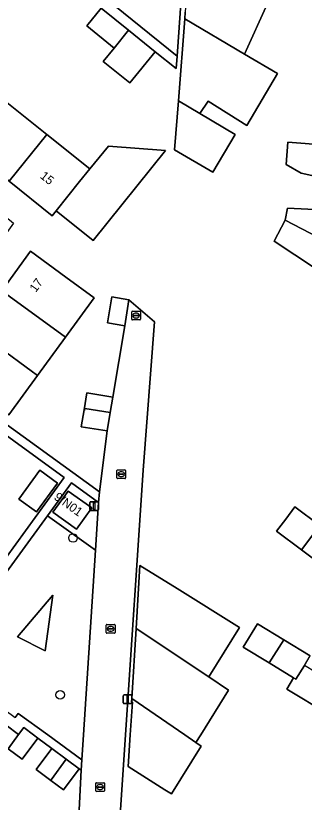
# Model space of a CAD drawing. Extents: x 160102 to 160934, y 382045 to 382923.
# Drawn here: x 160503.3 to 160536.3, y 382492.3 to 382582.2 of the extents above; entities that cross this region are included whole.
import ezdxf

# ---------------------------------------------------------------- set-up
doc = ezdxf.new("R2010")
doc.units = 0
for name, color, linetype in [('IMGEO_Boom', 7, 'Continuous'), ('IMGEO_Erf', 7, 'Continuous'), ('IMGEO_Groenvoorziening', 7, 'Continuous'), ('IMGEO_Kolk', 7, 'Continuous'), ('IMGEO_Lichtmast', 7, 'Continuous'), ('IMGEO_Pand', 7, 'Continuous'), ('IMGEO_Pand_nummerreeks', 7, 'Continuous'), ('IMGEO_Rijbaan_lokaal_open', 7, 'Continuous'), ('IMGEO_Voetpad_open', 7, 'Continuous')]:
    doc.layers.add(name, color=color, linetype=linetype)

msp = doc.modelspace()

# ---------------------------------------------------------------- linework, layer by layer
at = {"layer": 'IMGEO_Boom'}
for centre in [(160509.882, 382522.501), (160508.408, 382504.588)]:
    msp.add_circle(centre, 0.489, dxfattribs=at)
at = {"layer": 'IMGEO_Erf'}
for points in [[(160522.529, 382588.511), (160521.777, 382577.568), (160521.653, 382576.138), (160519.258, 382578.07), (160516.366, 382574.495), (160513.332, 382576.949), (160514.58, 382578.492), (160511.462, 382581.014), (160513.108, 382583.049)], [(160466.307, 382588.202), (160494.827, 382565.152), (160500, 382560.972), (160503.073, 382558.488), (160500, 382554.224), (160491.895, 382542.979), (160500, 382537.111), (160512.903, 382527.769), (160513.795, 382534.731), (160510.825, 382535.221), (160511.14, 382537.129), (160511.461, 382539.075), (160514.431, 382538.585), (160515.795, 382546.76), (160513.821, 382547.08), (160514.301, 382550.045), (160516.275, 382549.725), (160519.19, 382547.212), (160517.912, 382530.251), (160515.877, 382500), (160513.04, 382457.812)], [(160532.105, 382583.595), (160529.486, 382577.794), (160533.26, 382575.563), (160529.753, 382569.63), (160525.337, 382572.407), (160524.366, 382571.009), (160528.406, 382568.623), (160525.848, 382564.292), (160521.488, 382566.867), (160521.921, 382572.453), (160522.649, 382581.836), (160522.708, 382582.592)], [(160494.172, 382582.757), (160492.247, 382580.362), (160497.131, 382576.442), (160500, 382574.14), (160501.942, 382572.581), (160506.884, 382568.616), (160511.788, 382564.68), (160513.923, 382567.267), (160520.438, 382566.776), (160512.167, 382556.49), (160507.938, 382559.891), (160507.48, 382559.322), (160502.579, 382563.261), (160500, 382565.334), (160497.641, 382567.23), (160492.833, 382571.095), (160487.952, 382575.018), (160483.149, 382578.878), (160478.25, 382582.816)], [(160538.538, 382563.615), (160535.938, 382564.173), (160534.226, 382565.184), (160534.423, 382567.722), (160538.823, 382567.379)], [(160537.595, 382553.305), (160532.862, 382556.422), (160534.13, 382558.833), (160534.372, 382560.203), (160538.255, 382559.998)], [(160500, 382517.229), (160508.888, 382529.416), (160500, 382535.855)], [(160538.993, 382502.401), (160534.306, 382505.245), (160535.085, 382506.529), (160532.291, 382508.224), (160529.327, 382510.022), (160530.955, 382512.696), (160533.952, 382510.872), (160536.981, 382509.028)], [(160509.987, 382479.244), (160510.797, 382495.971), (160510.591, 382496.124), (160508.791, 382493.712), (160507.34, 382494.795), (160505.662, 382496.047), (160507.463, 382498.46), (160505.86, 382499.641), (160504.066, 382497.224), (160502.459, 382498.417), (160503.67, 382500.048), (160502.23, 382501.098), (160501.429, 382500), (160500.798, 382499.134), (160500, 382499.716), (160499.611, 382500), (160497.354, 382501.646), (160494.308, 382503.867), (160495.739, 382505.83), (160494.181, 382506.966), (160489.058, 382500), (160485.427, 382495.063), (160490.171, 382491.653)]]:
    msp.add_lwpolyline(points, dxfattribs=at)
for points in [[(160505.83, 382541.082), (160502.541, 382536.567), (160500, 382538.411), (160499.319, 382538.905), (160495.271, 382541.842), (160498.564, 382546.369), (160500, 382548.343), (160501.74, 382550.735), (160505.035, 382555.264), (160509.068, 382552.309), (160512.289, 382549.95), (160509.011, 382545.449)], [(160503.705, 382526.955), (160506.107, 382530.24), (160508.125, 382528.765), (160505.722, 382525.479)], [(160512.45, 382521.097), (160512.81, 382526.575), (160509.709, 382528.814), (160506.97, 382525.048)], [(160510.271, 382523.511), (160507.589, 382525.443), (160509.337, 382527.869), (160512.018, 382525.936)], [(160533.142, 382523.268), (160534.176, 382524.662), (160535.214, 382526.061), (160538.069, 382523.943), (160540.923, 382521.825), (160539.928, 382520.484), (160538.851, 382519.032), (160535.996, 382521.15)], [(160528.902, 382512.287), (160525.38, 382506.627), (160527.651, 382505.107), (160524.473, 382500), (160523.923, 382499.115), (160524.531, 382498.695), (160521.144, 382493.252), (160520.387, 382493.731), (160516.164, 382496.407), (160516.412, 382500), (160516.669, 382503.734), (160516.577, 382503.791), (160516.601, 382504.177), (160517.089, 382512.178), (160517.527, 382519.365), (160521.773, 382516.723)]]:
    msp.add_lwpolyline(points, close=True, dxfattribs=at)
at = {"layer": 'IMGEO_Groenvoorziening'}
for points in [[(160512.45, 382521.097), (160506.97, 382525.048), (160500, 382515.515), (160494.685, 382508.245), (160500, 382504.373), (160503.264, 382501.995), (160503.627, 382502.448), (160506.985, 382500), (160510.875, 382497.164), (160511.062, 382500)], [(160503.553, 382511.206), (160506.716, 382509.624), (160507.579, 382515.951)], [(160503.553, 382511.206), (160507.579, 382515.951), (160506.716, 382509.624)]]:
    msp.add_lwpolyline(points, close=True, dxfattribs=at)
at = {"layer": 'IMGEO_Kolk'}
for p, q in [((160516.583, 382547.492), (160516.583, 382548.344)), ((160516.658, 382548.418), (160517.51, 382548.418)), ((160517.071, 382548.198), (160517.096, 382548.198)), ((160517.584, 382548.344), (160517.584, 382547.492)), ((160517.51, 382547.418), (160516.658, 382547.418)), ((160516.842, 382547.912), (160516.842, 382547.924)), ((160517.28, 382547.875), (160516.882, 382547.875)), ((160516.885, 382547.961), (160517.283, 382547.961)), ((160517.094, 382547.638), (160517.069, 382547.638)), ((160517.326, 382547.924), (160517.326, 382547.912)), ((160514.887, 382529.366), (160514.887, 382530.218)), ((160514.962, 382530.292), (160515.814, 382530.292)), ((160515.375, 382530.072), (160515.4, 382530.072)), ((160515.888, 382530.218), (160515.888, 382529.366)), ((160515.814, 382529.292), (160514.962, 382529.292)), ((160515.146, 382529.786), (160515.146, 382529.798)), ((160515.584, 382529.749), (160515.186, 382529.749)), ((160515.189, 382529.835), (160515.587, 382529.835)), ((160515.398, 382529.512), (160515.373, 382529.512)), ((160515.63, 382529.798), (160515.63, 382529.786)), ((160513.68, 382511.695), (160513.68, 382512.547)), ((160513.755, 382512.621), (160514.607, 382512.621)), ((160513.939, 382512.115), (160513.939, 382512.127)), ((160513.982, 382512.164), (160514.38, 382512.164)), ((160514.168, 382512.401), (160514.193, 382512.401)), ((160514.423, 382512.127), (160514.423, 382512.115)), ((160514.681, 382512.547), (160514.681, 382511.695)), ((160514.607, 382511.621), (160513.755, 382511.621)), ((160514.377, 382512.078), (160513.979, 382512.078)), ((160514.191, 382511.841), (160514.166, 382511.841)), ((160512.479, 382493.616), (160512.479, 382494.468)), ((160512.554, 382494.542), (160513.406, 382494.542)), ((160512.967, 382494.322), (160512.992, 382494.322)), ((160513.48, 382494.468), (160513.48, 382493.616)), ((160513.406, 382493.542), (160512.554, 382493.542)), ((160512.738, 382494.036), (160512.738, 382494.048)), ((160513.176, 382493.999), (160512.778, 382493.999)), ((160512.781, 382494.085), (160513.179, 382494.085)), ((160512.99, 382493.762), (160512.965, 382493.762)), ((160513.222, 382494.048), (160513.222, 382494.036))]:
    msp.add_line(p, q, dxfattribs=at)
for points in [[(160516.583, 382547.492), (160516.583, 382548.344)], [(160516.658, 382548.418), (160517.51, 382548.418)], [(160517.584, 382548.344), (160517.584, 382547.492)], [(160517.51, 382547.418), (160516.658, 382547.418)], [(160514.887, 382529.366), (160514.887, 382530.218)], [(160514.962, 382530.292), (160515.814, 382530.292)], [(160515.888, 382530.218), (160515.888, 382529.366)], [(160515.814, 382529.292), (160514.962, 382529.292)], [(160513.68, 382511.695), (160513.68, 382512.547)], [(160513.755, 382512.621), (160514.607, 382512.621)], [(160514.681, 382512.547), (160514.681, 382511.695)], [(160514.607, 382511.621), (160513.755, 382511.621)], [(160512.479, 382493.616), (160512.479, 382494.468)], [(160512.554, 382494.542), (160513.406, 382494.542)], [(160513.48, 382494.468), (160513.48, 382493.616)], [(160513.406, 382493.542), (160512.554, 382493.542)]]:
    msp.add_lwpolyline(points, dxfattribs=at)
for centre, radius, start, end in [((160516.66, 382548.342), 0.0765, 91.55205, 178.44795), ((160516.66, 382548.342), 0.0765, 91.55205, 178.44795), ((160517.508, 382548.342), 0.0765, 1.55205, 88.44795), ((160517.508, 382548.342), 0.0765, 1.55205, 88.44795), ((160516.66, 382547.494), 0.0765, 181.55205, 268.44795), ((160516.66, 382547.494), 0.0765, 181.55205, 268.44795), ((160516.882, 382547.921), 0.0403, 85.87752, 175.75265), ((160516.879, 382547.911), 0.0366, 178.93798, 274.71019), ((160517.283, 382547.918), 0.043, 264.86636, 352.45326), ((160517.287, 382547.923), 0.0386, 1.73085, 96.63898), ((160517.508, 382547.494), 0.0765, 271.55205, 358.44795), ((160517.508, 382547.494), 0.0765, 271.55205, 358.44795), ((160514.964, 382530.216), 0.0765, 91.55205, 178.44795), ((160514.964, 382530.216), 0.0765, 91.55205, 178.44795), ((160515.812, 382530.216), 0.0765, 1.55205, 88.44795), ((160515.812, 382530.216), 0.0765, 1.55205, 88.44795), ((160514.964, 382529.368), 0.0765, 181.55205, 268.44795), ((160514.964, 382529.368), 0.0765, 181.55205, 268.44795), ((160515.186, 382529.795), 0.0403, 85.87752, 175.75265), ((160515.183, 382529.785), 0.0366, 178.93798, 274.71019), ((160515.587, 382529.792), 0.043, 264.86636, 352.45326), ((160515.591, 382529.797), 0.0386, 1.73085, 96.63898), ((160515.812, 382529.368), 0.0765, 271.55205, 358.44795), ((160515.812, 382529.368), 0.0765, 271.55205, 358.44795), ((160513.757, 382512.545), 0.0765, 91.55205, 178.44795), ((160513.757, 382512.545), 0.0765, 91.55205, 178.44795), ((160513.979, 382512.124), 0.0403, 85.87752, 175.75265), ((160513.976, 382512.114), 0.0366, 178.93798, 274.71019), ((160514.38, 382512.121), 0.043, 264.86636, 352.45326), ((160514.384, 382512.126), 0.0386, 1.73085, 96.63898), ((160514.605, 382512.545), 0.0765, 1.55205, 88.44795), ((160514.605, 382512.545), 0.0765, 1.55205, 88.44795), ((160513.757, 382511.697), 0.0765, 181.55205, 268.44795), ((160513.757, 382511.697), 0.0765, 181.55205, 268.44795), ((160514.605, 382511.697), 0.0765, 271.55205, 358.44795), ((160514.605, 382511.697), 0.0765, 271.55205, 358.44795), ((160512.556, 382494.466), 0.0765, 91.55205, 178.44795), ((160512.556, 382494.466), 0.0765, 91.55205, 178.44795), ((160513.404, 382494.466), 0.0765, 1.55205, 88.44795), ((160513.404, 382494.466), 0.0765, 1.55205, 88.44795), ((160512.556, 382493.618), 0.0765, 181.55205, 268.44795), ((160512.556, 382493.618), 0.0765, 181.55205, 268.44795), ((160512.778, 382494.045), 0.0403, 85.87752, 175.75265), ((160512.775, 382494.035), 0.0366, 178.93798, 274.71019), ((160513.179, 382494.042), 0.043, 264.86636, 352.45326), ((160513.183, 382494.047), 0.0386, 1.73085, 96.63898), ((160513.404, 382493.618), 0.0765, 271.55205, 358.44795), ((160513.404, 382493.618), 0.0765, 271.55205, 358.44795)]:
    msp.add_arc(centre, radius, start, end, dxfattribs=at)
for centre, major_axis, ratio, start_param, end_param in [((160517.07, 382547.918), (-0.387, 0.002), 0.722429, 4.712389, 7.853982), ((160517.095, 382547.918), (-0.39, 0.002), 0.717154, 1.570796, 4.712389), ((160515.374, 382529.792), (-0.387, 0.002), 0.722429, 4.712389, 7.853982), ((160515.399, 382529.792), (-0.39, 0.002), 0.717154, 1.570796, 4.712389), ((160514.167, 382512.121), (-0.387, 0.002), 0.722429, 4.712389, 7.853982), ((160514.192, 382512.121), (-0.39, 0.002), 0.717154, 1.570796, 4.712389), ((160512.966, 382494.042), (-0.387, 0.002), 0.722429, 4.712389, 7.853982), ((160512.991, 382494.042), (-0.39, 0.002), 0.717154, 1.570796, 4.712389)]:
    msp.add_ellipse(centre, major_axis=major_axis, ratio=ratio, start_param=start_param, end_param=end_param, dxfattribs=at)
at = {"layer": 'IMGEO_Lichtmast'}
for p, q in [((160511.81, 382525.749), (160511.81, 382526.549)), ((160511.81, 382526.549), (160511.81, 382525.749)), ((160511.91, 382526.649), (160512.7, 382526.649)), ((160512.7, 382526.649), (160511.91, 382526.649)), ((160512.8, 382526.549), (160512.8, 382525.749)), ((160512.8, 382525.749), (160512.8, 382526.549)), ((160512.7, 382525.649), (160511.91, 382525.649)), ((160511.91, 382525.649), (160512.7, 382525.649)), ((160515.629, 382503.671), (160515.629, 382504.471)), ((160515.629, 382504.471), (160515.629, 382503.671)), ((160515.729, 382504.571), (160516.519, 382504.571)), ((160516.519, 382504.571), (160515.729, 382504.571)), ((160516.619, 382504.471), (160516.619, 382503.671)), ((160516.619, 382503.671), (160516.619, 382504.471)), ((160516.519, 382503.571), (160515.729, 382503.571)), ((160515.729, 382503.571), (160516.519, 382503.571))]:
    msp.add_line(p, q, dxfattribs=at)
for points in [[(160512.23, 382526.524), (160512.38, 382526.524), (160512.38, 382525.774), (160512.23, 382525.774), (160512.23, 382526.524)], [(160516.049, 382504.446), (160516.199, 382504.446), (160516.199, 382503.696), (160516.049, 382503.696), (160516.049, 382504.446)]]:
    msp.add_lwpolyline(points, dxfattribs=at)
for centre, start, end in [((160511.91, 382526.549), 90, 180), ((160511.91, 382526.549), 90, 180), ((160512.7, 382526.549), 0, 90), ((160512.7, 382526.549), 360, 90), ((160511.91, 382525.749), 180, 270), ((160511.91, 382525.749), 180, 270), ((160512.7, 382525.749), 270, 0), ((160512.7, 382525.749), 270, 0), ((160515.729, 382504.471), 90, 180), ((160515.729, 382504.471), 90, 180), ((160516.519, 382504.471), 0, 90), ((160516.519, 382504.471), 360, 90), ((160515.729, 382503.671), 180, 270), ((160515.729, 382503.671), 180, 270), ((160516.519, 382503.671), 270, 0), ((160516.519, 382503.671), 270, 0)]:
    msp.add_arc(centre, 0.1, start, end, dxfattribs=at)
at = {"layer": 'IMGEO_Pand'}
for points in [[(160522.649, 382581.836), (160529.486, 382577.794), (160532.105, 382583.595), (160529.137, 382584.927), (160529.152, 382585.097), (160523.021, 382587.864), (160522.708, 382582.592)], [(160514.58, 382578.492), (160516.219, 382580.531), (160513.108, 382583.049), (160511.462, 382581.014)], [(160529.486, 382577.794), (160522.649, 382581.836), (160521.921, 382572.453), (160524.366, 382571.009), (160525.337, 382572.407), (160529.753, 382569.63), (160533.26, 382575.563)], [(160514.58, 382578.492), (160513.332, 382576.949), (160516.366, 382574.495), (160519.258, 382578.07), (160516.219, 382580.531)], [(160502.579, 382563.261), (160506.884, 382568.616), (160501.942, 382572.581), (160500, 382570.165), (160497.641, 382567.23), (160500, 382565.334)], [(160524.366, 382571.009), (160521.921, 382572.453), (160521.488, 382566.867), (160525.848, 382564.292), (160528.406, 382568.623)], [(160547.58, 382569.718), (160544.296, 382569.974), (160541.327, 382570.206), (160541.092, 382567.202), (160538.823, 382567.379), (160534.423, 382567.722), (160534.226, 382565.184), (160535.938, 382564.173), (160538.538, 382563.615), (160543.727, 382563.248), (160547.056, 382562.989), (160552.04, 382562.601), (160552.564, 382569.329)], [(160511.788, 382564.68), (160506.884, 382568.616), (160502.579, 382563.261), (160507.48, 382559.322), (160507.938, 382559.891), (160510.614, 382563.219)], [(160513.923, 382567.267), (160511.788, 382564.68), (160510.614, 382563.219), (160507.938, 382559.891), (160512.167, 382556.49), (160520.438, 382566.776)], [(160551.827, 382561.414), (160546.852, 382561.905), (160543.549, 382562.231), (160543.303, 382559.732), (160538.255, 382559.998), (160534.372, 382560.203), (160534.13, 382558.833), (160537.943, 382556.836), (160538.099, 382556.743), (160538.999, 382556.655), (160551.24, 382555.455)], [(160551.24, 382555.455), (160538.999, 382556.655), (160538.099, 382556.743), (160537.943, 382556.836), (160534.13, 382558.833), (160532.862, 382556.422), (160537.595, 382553.305), (160539.806, 382553.087), (160539.529, 382550.277), (160539.612, 382549.61), (160539.842, 382548.94), (160540.177, 382548.324), (160540.742, 382547.567), (160541.272, 382547.092), (160542.048, 382546.688), (160542.701, 382546.424), (160550.275, 382545.677), (160550.406, 382547), (160550.643, 382549.403)], [(160509.011, 382545.449), (160512.289, 382549.95), (160509.068, 382552.309), (160505.035, 382555.264), (160501.74, 382550.735)], [(160498.564, 382546.369), (160500, 382545.324), (160505.83, 382541.082), (160509.011, 382545.449), (160501.74, 382550.735), (160500, 382548.343)], [(160515.795, 382546.76), (160516.275, 382549.725), (160514.301, 382550.045), (160513.821, 382547.08)], [(160498.564, 382546.369), (160495.271, 382541.842), (160499.319, 382538.905), (160500, 382538.411), (160502.541, 382536.567), (160505.83, 382541.082), (160500, 382545.324)], [(160514.141, 382536.828), (160514.431, 382538.585), (160511.461, 382539.075), (160511.14, 382537.129), (160511.202, 382537.083), (160511.24, 382537.31)], [(160514.141, 382536.828), (160511.24, 382537.31), (160511.202, 382537.083), (160511.14, 382537.129), (160510.825, 382535.221), (160513.795, 382534.731)], [(160505.722, 382525.479), (160508.125, 382528.765), (160506.107, 382530.24), (160503.705, 382526.955)], [(160510.271, 382523.511), (160512.018, 382525.936), (160509.337, 382527.869), (160507.589, 382525.443)], [(160538.069, 382523.943), (160535.214, 382526.061), (160534.176, 382524.662), (160533.142, 382523.268), (160535.996, 382521.15)], [(160540.923, 382521.825), (160538.069, 382523.943), (160535.996, 382521.15), (160538.851, 382519.032), (160539.928, 382520.484)], [(160525.38, 382506.627), (160528.902, 382512.287), (160521.773, 382516.723), (160517.527, 382519.365), (160517.089, 382512.178)], [(160525.38, 382506.627), (160517.089, 382512.178), (160516.601, 382504.177), (160522.643, 382500), (160523.923, 382499.115), (160524.473, 382500), (160527.651, 382505.107)], [(160533.952, 382510.872), (160530.955, 382512.696), (160529.327, 382510.022), (160532.291, 382508.224)], [(160536.981, 382509.028), (160533.952, 382510.872), (160532.291, 382508.224), (160535.085, 382506.529), (160535.354, 382506.366), (160536.316, 382507.94)], [(160537.577, 382507.182), (160536.316, 382507.94), (160535.354, 382506.366), (160535.085, 382506.529), (160534.306, 382505.245), (160538.993, 382502.401), (160539.679, 382503.544), (160540.727, 382505.291)], [(160516.601, 382504.177), (160516.577, 382503.791), (160516.669, 382503.734), (160516.412, 382500), (160516.164, 382496.407), (160520.387, 382493.731), (160521.144, 382493.252), (160524.531, 382498.695), (160523.923, 382499.115), (160522.643, 382500)], [(160505.86, 382499.641), (160505.377, 382500), (160504.254, 382500.834), (160503.67, 382500.048), (160502.459, 382498.417), (160504.066, 382497.224)], [(160509.101, 382497.236), (160507.463, 382498.46), (160505.662, 382496.047), (160507.34, 382494.795), (160507.385, 382494.869)], [(160509.101, 382497.236), (160507.385, 382494.869), (160507.34, 382494.795), (160508.791, 382493.712), (160510.591, 382496.124)]]:
    msp.add_lwpolyline(points, close=True, dxfattribs=at)
at = {"layer": 'IMGEO_Rijbaan_lokaal_open'}
for points in [[(160482.098, 382608.167), (160482.828, 382609.057), (160500, 382595.174), (160521.777, 382577.568), (160522.529, 382588.511), (160523.188, 382598.313), (160523.787, 382607.377), (160524.568, 382619.515), (160524.9, 382624.057), (160525.288, 382624.05), (160525.477, 382626.898), (160516.443, 382636.034), (160510.687, 382632.435), (160500, 382625.753), (160480.01, 382613.255), (160480.277, 382612.822), (160464.977, 382593.454), (160462.972, 382590.915), (160466.307, 382588.202), (160468.365, 382590.761), (160472.653, 382596.093), (160480.439, 382606.115)], [(160508.547, 382462.296), (160508.479, 382461.121), (160513.04, 382457.812), (160515.877, 382500), (160517.912, 382530.251), (160519.19, 382547.212), (160516.275, 382549.725), (160515.795, 382546.76), (160514.431, 382538.585), (160514.141, 382536.828), (160513.795, 382534.731), (160512.903, 382527.769), (160512.81, 382526.575), (160512.45, 382521.097), (160511.062, 382500), (160510.875, 382497.164), (160510.797, 382495.971), (160509.987, 382479.244), (160509.669, 382479.278), (160509, 382469.155), (160508.837, 382466.683)]]:
    msp.add_lwpolyline(points, close=True, dxfattribs=at)
at = {"layer": 'IMGEO_Voetpad_open'}
msp.add_lwpolyline([(160509.632, 382585.855), (160513.108, 382583.049), (160516.219, 382580.531), (160519.258, 382578.07), (160521.653, 382576.138), (160521.777, 382577.568), (160500, 382595.174), (160482.828, 382609.057), (160482.098, 382608.167), (160485.25, 382605.608), (160487.051, 382604.16), (160490.204, 382601.612), (160493.678, 382598.805), (160496.997, 382596.104), (160499.909, 382593.734), (160500, 382593.66), (160503.402, 382590.901), (160506.643, 382588.276)], close=True, dxfattribs=at)
for points in [[(160500, 382515.515), (160506.97, 382525.048), (160509.709, 382528.814), (160512.81, 382526.575), (160512.903, 382527.769), (160500, 382537.111)], [(160500, 382535.855), (160508.888, 382529.416), (160500, 382517.229)], [(160502.23, 382501.098), (160503.67, 382500.048), (160504.254, 382500.834), (160505.377, 382500), (160505.86, 382499.641), (160507.463, 382498.46), (160509.101, 382497.236), (160510.591, 382496.124), (160510.797, 382495.971), (160510.875, 382497.164), (160506.985, 382500), (160503.627, 382502.448), (160503.264, 382501.995)]]:
    msp.add_lwpolyline(points, dxfattribs=at)

# ---------------------------------------------------------------- texts
at = {"layer": 'IMGEO_Pand_nummerreeks'}
for s, rotation, p in [('15', 321.21076, (160506.04, 382563.712)), ('17', 53.96552, (160505.628, 382550.502)), ('9/N01', 324.24611, (160507.623, 382526.994))]:
    msp.add_text(s, height=1, rotation=rotation, dxfattribs=at).set_placement(p)

doc.saveas('drawing.dxf')
